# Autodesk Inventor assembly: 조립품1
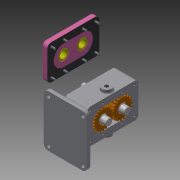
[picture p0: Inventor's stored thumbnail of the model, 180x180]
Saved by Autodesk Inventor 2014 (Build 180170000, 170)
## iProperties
Created: 2020-04
Part Number: 조립품1
Document SubType Name: Assembly
Designer: kh
Author: kh
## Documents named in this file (11)
- C:\Users\kh\Desktop\새 폴더\700407V1021\조립품1.iam
- C:\Users\kh\Desktop\새 폴더\700407V1021\본체.ipt
- C:\Users\kh\Desktop\새 폴더\700407V1021\개스킷.ipt
- C:\Users\kh\Desktop\새 폴더\700407V1021\메인축.ipt
- C:\Users\kh\Desktop\새 폴더\700407V1021\베어링부시.ipt
- C:\Users\kh\Desktop\새 폴더\700407V1021\볼트 M5.ipt
- C:\Users\kh\Desktop\새 폴더\700407V1021\서브축.ipt
- C:\Users\kh\Desktop\새 폴더\700407V1021\스퍼기어.ipt
- C:\Users\kh\Desktop\새 폴더\700407V1021\오일 실 16 28 7.ipt
- C:\Users\kh\Desktop\새 폴더\700407V1021\커버.ipt
- C:\Users\kh\Desktop\새 폴더\700407V1021\키 6 x 6 x 18.ipt
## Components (1 placed, 1 different names)
1. 개스킷:1 — 플러쉬:1, 플러쉬:2
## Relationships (2: Flush 2)
- 플러쉬:1 [Flush]: 개스킷:1
- 플러쉬:2 [Flush]: 개스킷:1
